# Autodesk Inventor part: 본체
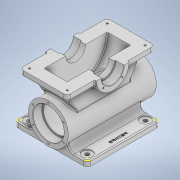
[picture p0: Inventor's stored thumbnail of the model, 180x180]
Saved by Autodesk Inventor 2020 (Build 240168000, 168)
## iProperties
Created: 2023-07
Part Number: 본체
Material: 일반
Document SubType Name: Modeling
Designer: home
Density: 1 g/cm^3
Appearance: 기본값
Mass: 2162.34 g
Surface Area: 2899.12 cm^2
Volume: 2162.34 cm^3
Author: home
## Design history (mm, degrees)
sketch "스케치1"
  geometry: C1 r 55 at (0, 0); 1 further point
  constraints: 1 centre point, 1 coincident
  dimensions: "d0" = 110 diameter of C1
extrude "돌출1" new body sketch "스케치1" stored distance "d1" = 242; taper "d2" = 0 deg
node "작업 평면1"
sketch "스케치2"
  geometry: L1 (55, 121)-(-55, 121) reference; L2 (55, 14)-(-55, 14); L3 (0, 14)-(0, 121); L4 (65, 134)-(-65, 134); L5 (-65, 134)-(-65, -106); L6 (-65, -106)-(65, -106); L7 (65, -106)-(65, 134); L8 (65, 134)-(-65, -106); L9 (-65, 134)-(65, -106); 1 further point
  constraints: 16 end point, 4 midpoint, 3 parallel, 1 horizontal, 1 perpendicular
  dimensions: "d4" = 107 distance between parallel lines of L1 L2; "d5" = 107 distance of L3.start L3.end; "d6" = 130 distance of L6.end L5.end; "d7" = 240 distance of L6.end L4.start
extrude "돌출2" join sketch "스케치2" distance "d8" = 15; taper "d9" = 0 deg
node "작업 평면2"
sketch "스케치3"
  geometry: L1 (0, 0)-(0, -15) reference; L2 (13, -50)-(13, -160) reference; L3 (13, -50)-(13, 0); L4 (120, 0)-(120, -50); L5 (120, -50)-(120, -160); L6 (240, 0)-(0, 0) reference; C1 r 100 at (120, 0); 3 further points
  constraints: 6 end point, 1 centre point, 1 coincident, 1 vertical, 1 other
  dimensions: "d11" = 107 distance between parallel lines of L3 L4; "d12" = 200 diameter of C1
extrude "돌출3" join sketch "스케치3" stored distance "d13" = 90; taper "d14" = 0 deg
sketch "스케치4"
  geometry: L1 (240, 0)-(0, 0) reference; C1 r 45 at (120, 0); 3 further points
  constraints: 1 centre point, 1 midpoint
  dimensions: "d15" = 90 diameter of C1
extrude "돌출4" join sketch "스케치4" stored distance "d16" = 140; taper "d17" = 0 deg
sketch "스케치5"
  geometry: C1 r 31 at (120, 0); A1 r 45 centre (120, 0) between (75, 0) and (165, 0) reference; 1 further point
  constraints: 1 centre point, 1 coincident
  dimensions: "d18" = 62 diameter of C1
extrude "돌출5" cut sketch "스케치5" distance "d19" = 23; taper "d20" = 0 deg
sketch "스케치7"
  geometry: L1 (75, 0)-(165, 0) reference; C1 r 87 at (120, 0); 1 further point
  constraints: 1 centre point, 1 midpoint
  dimensions: "d21" = 174 diameter of C1
extrude "돌출6" cut sketch "스케치7" stored distance "d22" = 64; taper "d23" = 0 deg
sketch "스케치8"
  geometry: L1 (89, 0)-(151, 0) reference; C1 r 27.5 at (120, 0); A1 r 31 centre (120, 0) between (89, 0) and (151, 0) reference; 1 further point
  constraints: 1 centre point, 1 coincident
  dimensions: "d24" = 55 diameter of C1
extrude "돌출7" cut sketch "스케치8" stored distance "d25" = 64; taper "d26" = 0 deg
sketch "스케치9"
  geometry: 1 further point
sketch "스케치10"
  geometry: L1 (-55, -14)-(55, -14) reference; L2 (-55, 93)-(55, 93); L3 (0, 0)-(0, 93); L4 (52, 0)-(52, 93); L5 (-52, 0)-(-52, 93); L6 (-55, -121)-(55, -121) reference; 4 further points
  constraints: 8 end point, 3 parallel, 2 coincident, 2 symmetric about line, 1 midpoint
  dimensions: "d27" = 107 distance between parallel lines of L1 L2; "d28" = 93 distance of L3.start L3.end; "d29" = 52 distance between parallel lines of L3 L4; "d30" = 52 distance between parallel lines of L3 L5
hole "구멍1" sketch "스케치10" at (-52, -121), (52, -121), (52, 93), (-52, 93) diameter "d31" = 4.917; stored, may be unused: countersink angle "d35" = 90 deg, drill point angle "d37" = 0 deg; dims "d32" = 12, "d33" = 4, "d34" = 2, "d36" = 17.1
sketch "스케치11"
  geometry: L1 (120, 0)-(120, -37); L2 (120, 0)-(93.837, -26.163); L3 (120, 0)-(146.163, -26.163); A1 r 45 centre (120, 0) between (75, 0) and (165, 0) reference; A2 r 37 centre (120, 0) between (120, -37) and (93.837, -26.163); 3 further points
  constraints: 6 end point, 3 coincident, 3 point on circle, 1 centre point, 1 vertical
  dimensions: "d38" = 74 diameter of A2; "d39" = 45 deg angle of L2 L1; "d40" = 45 deg angle of L1 L3
hole "구멍2" sketch "스케치11" at (93.837, -26.163), (146.163, -26.163) diameter "d41" = 4.134; stored, may be unused: countersink angle "d45" = 90 deg, drill point angle "d47" = 118 deg; dims "d42" = 10, "d43" = 4, "d44" = 2, "d46" = 12
sketch "스케치12"
  geometry: L1 (55, 121)-(-55, 121) reference; L2 (0, 121)-(0, -121); L3 (-55, -121)-(55, -121) reference; L4 (42.5, 121)-(42.5, 96); L5 (42.5, 96)-(38.5, 96); L6 (38.5, 96)-(38.5, -96); L7 (38.5, -96)-(42.5, -96); L8 (42.5, -96)-(42.5, -121); L9 (42.5, 121)-(0, 121); L10 (42.5, -121)-(0, -121); 1 further point
  constraints: 16 end point, 4 perpendicular, 4 point on line, 2 midpoint, 1 collinear, 1 horizontal
  dimensions: "d48" = 85 diameter of L4 L2; "d49" = 25 distance of L4.start L4.end; "d50" = 25 distance of L7.end L8.end; "d51" = 77 diameter of L6 L2
revolve "회전1" sketch "스케치12" stored, may be unused: angle "d52" = 90 deg
sketch "스케치13"
  geometry: L1 (0, 48.5)-(0, -48.5); L2 (-48.5, 0)-(48.5, 0); L3 (0, 0)-(42.002, 24.25); L4 (0, 0)-(-42.002, 24.25); L5 (0, 0)-(-42.002, -24.25); L6 (0, 0)-(42.002, -24.25); C1 r 42.5 at (0, 0) reference; A1 r 48.5 centre (0, 0) between (0, 48.5) and (0, -48.5); 7 further points
  constraints: 12 end point, 7 coincident, 6 point on circle, 2 symmetric about line, 1 centre point, 1 horizontal, 1 vertical
  dimensions: "d53" = 97 diameter of A1; "d54" = 97 distance of L1.start L1.end; "d55" = 97 distance of L2.start L2.end; "d56" = 60 deg angle of L1 L4; "d57" = 60 deg angle of L1 L3
hole "구멍3" sketch "스케치13" at (-42.002, 24.25), (0, 48.5), (42.002, 24.25), (42.002, -24.25), (0, -48.5), (-42.002, -24.25) diameter "d58" = 4.134; stored, may be unused: countersink angle "d62" = 90 deg, drill point angle "d64" = 118 deg; dims "d59" = 10, "d60" = 4, "d61" = 2, "d63" = 12
node "작업 평면3"
sketch "스케치14"
  geometry: L1 (0, 243.4)-(0, -256.4) reference; L2 (-55, -121)-(55, -121) reference; L3 (-100, -114)-(100, -114); L4 (-100, 86)-(100, 86); L5 (-100, 172)-(-100, -185); L6 (100, 172)-(100, -185); 1 further point
  constraints: 8 end point, 4 parallel, 4 point on line
  dimensions: "d66" = 7 distance between parallel lines of L2 L3; "d67" = 200 distance between parallel lines of L3 L4; "d68" = 100 distance between parallel lines of L1 L5; "d69" = 100 distance between parallel lines of L1 L6
extrude "돌출8" join sketch "스케치14" distance "d70" = 15; taper "d71" = 0 deg
sketch "스케치15"
  geometry: L1 (-55, -121)-(55, -121) reference; L2 (-55, -14)-(100, -14); L3 (100, -114)-(100, 86) reference; L4 (-55, -94)-(100, -94); L5 (-55, 66)-(100, 66); L6 (0, -94)-(0, 66); L7 (80, -94)-(80, 66); L8 (-80, -94)-(-80, 66); C1 r 14 at (80, 66); C2 r 14 at (80, -94); 1 further point
  constraints: 12 end point, 5 parallel, 3 point on line, 2 centre point, 2 coincident, 1 midpoint, 1 perpendicular
  dimensions: "d72" = 107 distance between parallel lines of L1 L2; "d73" = 80 distance between parallel lines of L2 L4; "d74" = 80 distance between parallel lines of L2 L5; "d76" = 80 distance between parallel lines of L6 L7; "d77" = 80 distance between parallel lines of L6 L8; "d78" = 28 diameter of C1; "d79" = 28 diameter of C2; "d80" = 80 distance from line of L2 L7.end; "d81" = 80 distance from line of L2 C2.centre
fillet "모깎기1" dims "d75" = 10
sketch "스케치16"
  geometry: A1 r 10 centre (90, 76) between (100, 76) and (90, 86) reference; A2 r 10 centre (90, -104) between (90, -114) and (100, -104) reference; A3 r 10 centre (-90, -104) between (-100, -104) and (-90, -114) reference; A4 r 10 centre (-90, 76) between (-90, 86) and (-100, 76) reference; 1 further point
extrude "돌출9" cut sketch "스케치15" distance "d82" = 2; taper "d83" = 0 deg
sketch "스케치17"
  geometry: C1 r 14 at (0, 0) reference; C2 r 5.5 at (0, 0); 1 further point
  constraints: 1 centre point, 1 coincident
  dimensions: "d84" = 11 diameter of C2
extrude "돌출10" cut sketch "스케치17" extent not by distance; stored distance "d85" = 0; taper "d86" = 0 deg
sketch "스케치18"
  geometry: C1 r 14 at (0, 0) reference; C2 r 5.5 at (0, 0); 1 further point
  constraints: 1 centre point, 1 coincident
  dimensions: "d87" = 11 diameter of C2
extrude "돌출11" cut sketch "스케치18" extent not by distance; stored distance "d88" = 0; taper "d89" = 0 deg
node "작업 평면4"
fillet "모깎기5" dims "d94" = 15
fillet "모깎기6" dims "d95" = 3
fillet "모깎기7" dims "d96" = 3
fillet "모깎기8" dims "d97" = 3
fillet "모깎기9" dims "d98" = 3
fillet "모깎기10" dims "d99" = 3
fillet "모깎기11" dims "d100" = 3
fillet "모깎기15" dims "d104" = 10
fillet "모깎기16" dims "d105" = 3
fillet "모깎기17" dims "d106" = 3
fillet "모깎기18" dims "d107" = 3
chamfer "모따기1" distance "d108" = 1; stored, may be unused: second distance "d109" = 2, angle "d110" = 45 deg
fillet "모깎기19" dims "d111" = 1
chamfer "모따기2" distance "d112" = 1; stored, may be unused: second distance "d113" = 2, angle "d114" = 45 deg
fillet "모깎기20" dims "d115" = 1.1
fillet "모깎기21" dims "d116" = 3
fillet "모깎기22" dims "d117" = 3
fillet "모깎기23" dims "d118" = 3
sketch "스케치19"
  geometry: L1 (100, -104)-(100, 76) reference; L2 (85, -104)-(85, 76); L3 (70, -59)-(70, 31) reference; L4 (69, 17)-(69, -45) reference; L5 (-55, -121)-(55, -121) reference; L6 (-55, -14)-(85, -14); 3 further points
  constraints: 4 end point, 2 midpoint, 2 parallel, 1 coincident, 1 other
  dimensions: "d119" = 15 distance between parallel lines of L1 L2; "d120" = 107 distance between parallel lines of L5 L6
feature "엠보싱1" sketch "스케치19" dims "d121" = 0.5, "d122" = 0
node "솔리드1"
mirror "미러1"
mirror "미러2"
mirror "미러3"
mirror "미러4"
mirror "미러5"
mirror "미러6"
node "투영된 루프1"
feature "A9D066F2-1C7D-4E18-AEED-F7BC21143FA4" dims "d41" = 4.134, "d42" = 10, "d43" = 4, "d44" = 2, "d45" = 90 deg, "d46" = 12, "d47" = 118 deg
other parameters: "d3" = 105, "d10" = -65, "d65" = -165
